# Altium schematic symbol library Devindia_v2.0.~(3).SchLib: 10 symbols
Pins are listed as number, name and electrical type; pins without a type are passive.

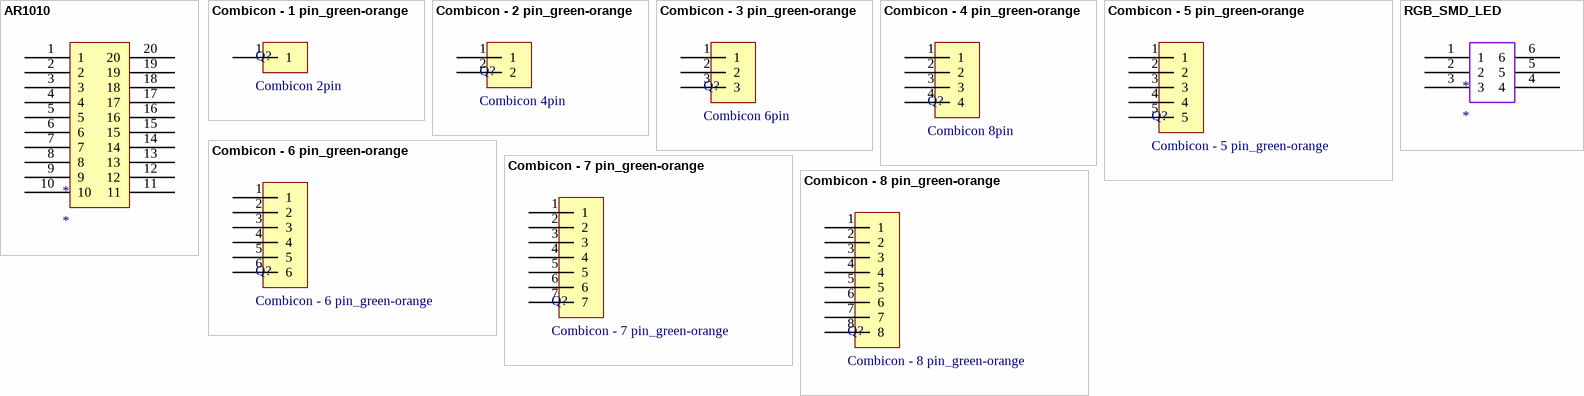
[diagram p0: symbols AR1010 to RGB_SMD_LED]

## AR1010
designator *
footprint AR1010
pins: 1, 2, 3, 4, 5, 6, 7, 8, 9, 10, 11, 12, 13, 14, 15, 16, 17, 18, 19, 20

## Combicon - 1 pin_green-orange
designator Q?, comment Combicon 2pin
footprint Combicon - 2 pin
pins: 1

## Combicon - 2 pin_green-orange
designator Q?, comment Combicon 4pin
footprint Combicon - 4pin
pins: 1, 2

## Combicon - 3 pin_green-orange
designator Q?, comment Combicon 6pin
footprint Combicon - 6pin
pins: 1, 2, 3

## Combicon - 4 pin_green-orange
designator Q?, comment Combicon 8pin
footprint Combicon - 8pin
pins: 1, 2, 3, 4

## Combicon - 5 pin_green-orange
designator Q?
footprint Combicon - 10 pin
pins: 1, 2, 3, 4, 5

## Combicon - 6 pin_green-orange
designator Q?
footprint Combicon - 12pin
pins: 1, 2, 3, 4, 5, 6

## Combicon - 7 pin_green-orange
designator Q?
footprint Combicon - 14pin
pins: 1, 2, 3, 4, 5, 6, 7

## Combicon - 8 pin_green-orange
designator Q?
footprint Combicon - 16pin
pins: 1, 2, 3, 4, 5, 6, 7, 8

## RGB_SMD_LED
designator *
footprint RGB_SMD_LED
pins: 1, 2, 3, 4, 5, 6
